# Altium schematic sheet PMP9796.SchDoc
size 431 x 279 mm; Date: Not shown in title block; ApprovedBy: Not shown in title block; CheckedBy: Not shown in title block; Author: Not shown in title block; CompanyName: Not shown in title block; Engineer: Not shown in title block; Organization: Not shown in title block; Address1: Not shown in title block; Address2: Not shown in title block; Address3: Not shown in title block; Address4: Not shown in title block; DocumentNumber: 1; Revision: Use project parameter SCH_Rev; SheetNumber: 2; SheetTotal: 3; PageSetup: Record=PageOptions¦CenterHorizontal=True¦CenterVertical=True¦PrintScale=1.00¦XCorrection=1.00¦YCorrection=1.00¦PrintKind=0¦BorderSize=5000000¦LeftOffset=0¦BottomOffset=0¦Orientation=2¦PaperLength=1000¦PaperWidth=1000¦Scale=100¦PaperSource=15¦PrintQuality=600¦MediaType=1¦DitherType=10¦PaperKind=Letter¦PrintScaleMode=1
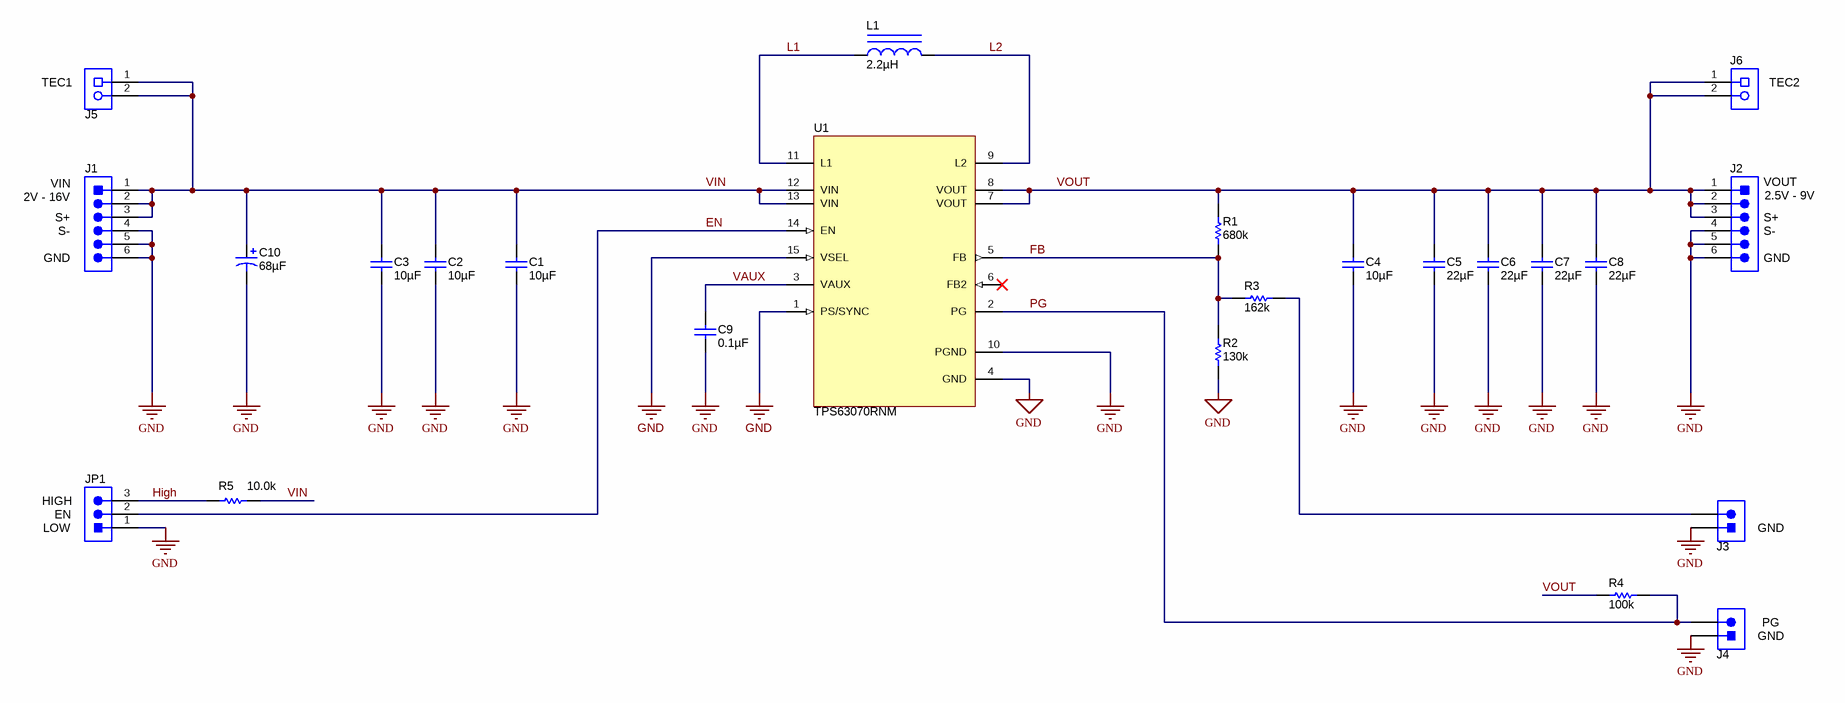
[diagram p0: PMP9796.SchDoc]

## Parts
C1  ValueDisplayed: 10µF  [0603]  (hidden comment: GRM188R61E106MA73D)
C2  ValueDisplayed: 10µF  [0805_HV]  (hidden comment: GRM21BC71E106ME11L)
C3  ValueDisplayed: 10µF  [0805_HV]  (hidden comment: GRM21BC71E106ME11L)
C4  ValueDisplayed: 10µF  [0603]  (hidden comment: GRM188R61E106MA73D)
C5  ValueDisplayed: 22µF  [0805_HV]  (hidden comment: GRM21BC81C226ME44L)
C6  ValueDisplayed: 22µF  [0805_HV]  (hidden comment: GRM21BC81C226ME44L)
C7  ValueDisplayed: 22µF  [0805_HV]  (hidden comment: GRM21BC81C226ME44L)
C8  ValueDisplayed: 22µF  [0805_HV]  (hidden comment: GRM21BC81C226ME44L)
C9  ValueDisplayed: 0.1µF  [0402]  (hidden comment: GRM155R71E104KE14D)
C10  ValueDisplayed: 68µF  [7343-31]  (hidden comment: T495D686K020ATE150)
J1  TSW-106-07-G-S  [TSW-106-07-G-S]  (value not drawn)
J2  TSW-106-07-G-S  [TSW-106-07-G-S]  (value not drawn)
J3  TSW-102-07-G-S  [TSW-102-07-G-S]  (value not drawn)
J4  TSW-102-07-G-S  [TSW-102-07-G-S]  (value not drawn)
J5  ED555/2DS  [TERM_BLK_ED555-2DS]  (value not drawn)
J6  ED555/2DS  [TERM_BLK_ED555-2DS]  (value not drawn)
JP1  TSW-103-07-G-S  [TSW-103-07-G-S]  (value not drawn)
L1  ValueDisplayed: 2.2µH  [XAL4020]  (hidden comment: XAL4020-222MEB)
R1  ValueDisplayed: 680k  [0603]  (hidden comment: RC0603FR-07680KL)
R2  ValueDisplayed: 130k  [0603]  (hidden comment: RC0603FR-07130KL)
R3  ValueDisplayed: 162k  [0603]  (hidden comment: RC0603FR-07162KL)
R4  ValueDisplayed: 100k  [0603]  (hidden comment: RC0603FR-07100KL)
R5  ValueDisplayed: 10.0k  [0603]  (hidden comment: CRCW060310K0FKEA)
U1  TPS63070RNM  [RNM0015A]

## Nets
GND: C1.2 C2.2 C3.2 C4.2 C5.2 C6.2 C7.2 C8.2 C9.2 C10.2(-) J1.4 J1.5 J1.6 J2.4 J2.5 J2.6 J3.1 J4.1 JP1.1 R2.1 U1.1(PS/SYNC) U1.4(GND) U1.10(PGND) U1.15(VSEL)
EN: JP1.2 U1.14(EN)
FB: R1.1 R2.2 R3.2 U1.5(FB)
High: JP1.3 R5.1
L1: L1.1 U1.11(L1)
L2: L1.2 U1.9(L2)
PG: J4.2 R4.2 U1.2(PG)
VAUX: C9.1 U1.3(VAUX)
VIN: C1.1 C2.1 C3.1 C10.1(+) J1.1 J1.2 J1.3 J5.1 J5.2 R5.2 U1.12(VIN) U1.13(VIN)
VOUT: C4.1 C5.1 C6.1 C7.1 C8.1 J2.1 J2.2 J2.3 J6.1 J6.2 R1.2 R4.1 U1.7(VOUT) U1.8(VOUT)
NetJ3_2: J3.2 R3.1

Not connected (* = marked no-connect by the designer): U1 6(FB2)*

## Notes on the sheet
- (near J5) TEC1
- (near J6) TEC2
- (near J1) 2V - 16V
- (near J1) VIN
- (near J1) S+
- (near J2) 2.5V - 9V
- (near J2) S+
- (near J2) VOUT
- (near J1) GND
- (near J1) S-
- (near J2) S-
- (near J2) GND
- (near JP1) HIGH
- (near JP1) LOW
- (near JP1) EN
- (near J3) GND
- (near J4) PG
- (near J4) GND

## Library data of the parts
C1 C4 = GRM188R61E106MA73D: CAP, CERM, 10 µF, 25 V, +/- 20%, X5R, 0603; Manufacturer: MuRata; Polarized: N; CompType: Capacitor; Value: 10uF; U/M: EA; Cap_F: 0.00001; Tolerance_%: 20; Value1: Unknown; VDC_V: 25; Value2: 25V; TaMin_C: -55; TaMax_C: 85; AEC Category: Q200
C2 C3 = GRM21BC71E106ME11L: CAP, CERM, 10 µF, 25 V, +/- 20%, X7S, 0805; Manufacturer: MuRata; Polarized: N; CompType: Capacitor; Value: 10uF; U/M: EA; Cap_F: 0.00001; Tolerance_%: 20; Value1: Unknown; VDC_V: 25; Value2: 25V; TaMin_C: -55; TaMax_C: 125; Cap_Case: 0805; AEC Category: Q200
C5-C8 = GRM21BC81C226ME44L: CAP, CERM, 22 µF, 16 V, +/- 20%, X6S, 0805; Manufacturer: MuRata; Polarized: N; CompType: Capacitor; Value: 22uF; U/M: EA; Cap_F: 0.000022; Tolerance_%: 20; Value1: Unknown; VDC_V: 16; Value2: 16V; TaMin_C: -55; TaMax_C: 105; Cap_Case: 0805; AEC Category: Q200
C9 = GRM155R71E104KE14D: CAP, CERM, 0.1 µF, 25 V, +/- 10%, X7R, 0402; Manufacturer: MuRata; Polarized: N; CompType: Capacitor; Value: 0.1uF; U/M: EA; Cap_F: 0.0000001; Tolerance_%: 10; Value1: Unknown; VDC_V: 25; Value2: 25V; TaMin_C: -55; TaMax_C: 125; AEC Category: Q200
C10 = T495D686K020ATE150: CAP, TA, 68 µF, 20 V, +/- 10%, 0.15 ohm, SMD; Manufacturer: Kemet; Polarized: Y; CompType: Capacitor; Value: 68uF; U/M: EA; Cap_F: 0.000068; Tolerance_%: 10; VDC_V: 20; Value2: 20V; ESR_ohm: 0.15; IRMS_A: 0.9; TaMin_C: -55; TaMax_C: 125; Cap_Case: D
J1 J2 = TSW-106-07-G-S: Header, 100mil, 6x1, Gold, TH; Manufacturer: Samtec; SymbolCreator: a0412235; U/M: EA
J3 J4 = TSW-102-07-G-S: Header, 100mil, 2x1, Gold, TH; Manufacturer: Samtec; SymbolCreator: a0412235; U/M: EA
J5 J6 = ED555/2DS: Terminal Block, 3.5mm Pitch, 2x1, TH; Manufacturer: On-Shore Technology; SymbolCreator: a0412235; Pitch_mm: 3.5; Gender: Female; Shrouded: N; Row_Count: 1; ContactFinish: Brass; Current_A: 6; Voltage_V: 150; Cert_CULUS: Y
JP1 = TSW-103-07-G-S: Header, 100mil, 3x1, Gold, TH; Manufacturer: Samtec; SymbolCreator: a0799628; U/M: EA
L1 = XAL4020-222MEB: Inductor, Shielded, Composite, 2.2 µH, 5.5 A, 0.04 ohm, SMD; Manufacturer: Coilcraft; Value: 2.2uH; Ind_H: 2.2E-6; Imax_A: 5.5; Irms: 5.5A @ 40C rise; Isat: 5.62A @ 30% inductance drop; DCR_ohm: 0.04; Value2: 5.5A; AEC Category: Q200
R1 = RC0603FR-07680KL: RES, 680 k, 1%, 0.1 W, 0603; Manufacturer: Yageo America; CompType: Resistor; Value: 680k; Res_ohm: 680000; Tolerance_%: 1; Power_W: 0.1; Value2: 0.1W; VDC_V: 150; TempCo: 200 ppm/C; U/M: EA; AEC Category: Q200
R2 = RC0603FR-07130KL: RES, 130 k, 1%, 0.1 W, 0603; Manufacturer: Yageo America; CompType: Resistor; Value: 130k; Res_ohm: 130000; Tolerance_%: 1; Power_W: 0.1; Value2: 0.1W; VDC_V: 150; TempCo: 200 ppm/C; EIA_Code: E96; U/M: EA; AEC Category: Q200
R3 = RC0603FR-07162KL: RES, 162 k, 1%, 0.1 W, 0603; Manufacturer: Yageo America; CompType: Resistor; Value: 162k; Res_ohm: 162000; Tolerance_%: 1; Power_W: 0.1; Value2: 0.1W; VDC_V: 150; TempCo: 200 ppm/C; EIA_Code: E96; U/M: EA; AEC Category: Q200
R4 = RC0603FR-07100KL: RES, 100 k, 1%, 0.1 W, 0603; Manufacturer: Yageo America; CompType: Resistor; Value: 100k; Res_ohm: 100000; Tolerance_%: 1; Power_W: 0.1; Value2: 0.1W; VDC_V: 150; TempCo: 200 ppm/C; EIA_Code: E96; U/M: EA
R5 = CRCW060310K0FKEA: RES, 10.0 k, 1%, 0.1 W, 0603; Manufacturer: Vishay-Dale; CompType: Resistor; Value: 10.0k; Res_ohm: 10000; Value_Code: 10k0; Tolerance_%: 1; Power_W: 0.1; Value2: 0.1W; VDC_V: 75; TempCo: 100 ppm/C; EIA_Code: E96; U/M: EA; AEC Category: Q200
U1 = TPS63070RNM: TPS63070RNM, RNM0015A; Manufacturer: Texas Instruments; SymbolCreator: Altium; SizeX_mm: 2.5; SizeY_mm: 3; SizeZ_mm: 1; CompType: IC; U/M: EA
